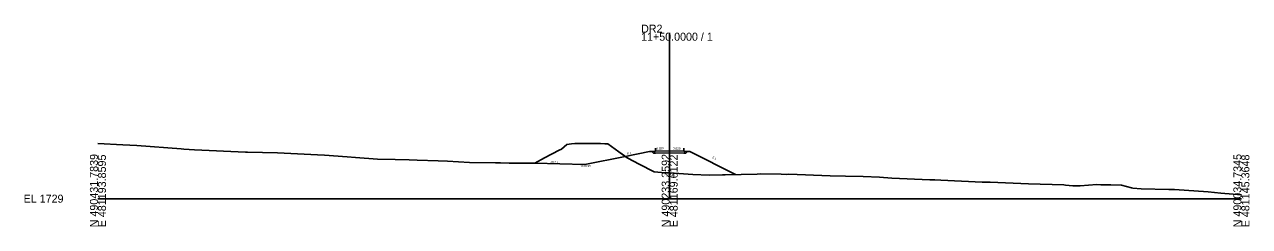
# Model space of a CAD drawing. Extents: x -26 to 403, y -10 to 2576.
# Drawn here: x -25.7 to 402.8, y 1490.3 to 1560.8 of the extents above; entities that cross this region are included whole.
import ezdxf

# ---------------------------------------------------------------- set-up
doc = ezdxf.new("R2010")
doc.units = 0
for name, color, linetype in [('Exist Cross Section Cell', 7, 'Continuous'), ('Exist XS Center Line Elevation Label', 7, 'Continuous'), ('Exist XS Ground Line', 7, 'Continuous'), ('Prop Road Sect_ Boring - Header (ID Tx)', 7, 'Continuous'), ('Prop XS Ditch Standard Text', 7, 'Continuous'), ('Prop XS Dump Level', 7, 'Continuous'), ('Prop XS Earthwork Shape', 7, 'Continuous'), ('Prop XS EOT Tick Mark', 7, 'Continuous'), ('Prop XS Finish Grade', 7, 'Continuous'), ('Prop XS Finish Grade Earthwork', 7, 'Continuous'), ('Prop XS Finish Grade Pavement', 7, 'Continuous'), ('Prop XS Pvmt Edge Slope', 7, 'Continuous'), ('Prop XS SE Text', 7, 'Continuous'), ('Prop XS Side Slope Text', 7, 'Continuous'), ('Prop XS Subgrade Earthwork', 7, 'Continuous')]:
    doc.layers.add(name, color=color, linetype=linetype)

msp = doc.modelspace()

# ---------------------------------------------------------------- linework, layer by layer
at = {"layer": 'Exist Cross Section Cell'}
for p, q in [((200, 1500), (200, 1557.94)), ((0, 1500), (200, 1500)), ((200, 1500), (400, 1500))]:
    msp.add_line(p, q, dxfattribs=at)
at = {"layer": 'Exist XS Ground Line'}
msp.add_lwpolyline([(0, 1519.31), (8.74, 1518.81), (13.56, 1518.54), (29.14, 1517.35), (30.03, 1517.29), (33.75, 1517.09), (51.66, 1516.26), (52.26, 1516.2), (62.83, 1515.95), (76.82, 1515.27), (79.27, 1515.16), (87.16, 1514.55), (90.07, 1514.37), (97.8, 1513.81), (103.94, 1513.71), (108.82, 1513.56), (111.71, 1513.43), (119.03, 1513.2), (122.32, 1513.05), (130.01, 1512.67), (139.06, 1512.48), (140.2, 1512.46), (140.88, 1512.49), (143.86, 1512.43), (152.84, 1512.38), (156.17, 1514.28), (161.31, 1516.93), (162.12, 1517.34), (164.07, 1518.92), (165.62, 1519.11), (166.82, 1519.26), (169.11, 1519.25), (175.8, 1519.23), (177.3, 1519.12), (178.39, 1519.09), (182.19, 1516.39), (185.34, 1514.15), (189.37, 1511.99), (194.6, 1509.38), (198.43, 1509.08), (200, 1508.98), (208.12, 1508.44), (213.79, 1508.26), (230.62, 1508.61), (231.88, 1508.62), (238.95, 1508.52), (240.84, 1508.49), (241.68, 1508.52), (256.16, 1507.93), (261.46, 1507.87), (267.67, 1507.73), (273.45, 1507.53), (277.74, 1507.2), (291.02, 1506.62), (292.78, 1506.56), (294.82, 1506.47), (309.34, 1505.77), (310.62, 1505.8), (312.17, 1505.72), (325.58, 1505.14), (337.91, 1504.8), (338.46, 1504.76), (341.06, 1504.54), (343.6, 1504.5), (349.42, 1504.96), (350.84, 1504.78), (354.32, 1504.89), (358.09, 1504.66), (361.61, 1503.77), (361.99, 1503.69), (364.96, 1503.45), (374.67, 1503.26), (375.3, 1503.21), (376.62, 1503.16), (388.4, 1502.42), (392.84, 1501.92), (400, 1501.31)], dxfattribs=at)
at = {"layer": 'Prop Road Sect_ Boring - Header (ID Tx)'}
for points in [[(195, 1516.61), (194.32, 1515.93), (193.74, 1516.51)], [(205.68, 1515.93), (206.26, 1516.51), (205, 1516.61)]]:
    msp.add_lwpolyline(points, close=True, dxfattribs=at)
at = {"layer": 'Prop XS Dump Level'}
for p, q in [((195, 1516.61), (200, 1516.71)), ((200, 1516.71), (205, 1516.61))]:
    msp.add_line(p, q, dxfattribs=at)
at = {"layer": 'Prop XS Earthwork Shape'}
for p, q in [((165.62, 1519.11), (164.07, 1518.92)), ((156.17, 1514.28), (152.84, 1512.38)), ((161.31, 1516.93), (156.17, 1514.28)), ((170.38, 1511.95), (184.49, 1514.76)), ((184.49, 1514.76), (182.19, 1516.39)), ((152.84, 1512.38), (170.38, 1511.95))]:
    msp.add_line(p, q, dxfattribs=at)
for points in [[(164.07, 1518.92), (162.12, 1517.34), (161.31, 1516.93)], [(169.11, 1519.25), (166.82, 1519.26), (165.62, 1519.11)], [(177.3, 1519.12), (175.8, 1519.23), (169.11, 1519.25)], [(182.19, 1516.39), (178.39, 1519.09), (177.3, 1519.12)], [(184.49, 1514.76), (184.49, 1514.76)]]:
    msp.add_lwpolyline(points, dxfattribs=at)
msp.add_lwpolyline([(195, 1515.94), (194.32, 1515.93), (193.74, 1516.51), (193, 1516.45), (184.49, 1514.76), (185.34, 1514.15), (189.37, 1511.99), (194.6, 1509.38), (198.43, 1509.08), (200, 1508.98), (208.12, 1508.44), (213.79, 1508.26), (222.99, 1508.45), (207, 1516.45), (206.26, 1516.51), (205.68, 1515.93), (205, 1515.94), (200, 1516.04)], close=True, dxfattribs=at)
at = {"layer": 'Prop XS EOT Tick Mark'}
for p, q in [((195, 1516.61), (195, 1517.61)), ((205, 1516.61), (205, 1517.61))]:
    msp.add_line(p, q, dxfattribs=at)
at = {"layer": 'Prop XS Finish Grade'}
for p, q in [((195, 1516.61), (193.74, 1516.51)), ((205, 1516.61), (206.26, 1516.51))]:
    msp.add_line(p, q, dxfattribs=at)
at = {"layer": 'Prop XS Finish Grade Earthwork'}
for p, q in [((170.38, 1511.95), (184.49, 1514.76)), ((193, 1516.45), (184.49, 1514.76)), ((193.74, 1516.51), (193, 1516.45)), ((206.26, 1516.51), (207, 1516.45)), ((207, 1516.45), (222.99, 1508.45)), ((152.84, 1512.38), (170.38, 1511.95))]:
    msp.add_line(p, q, dxfattribs=at)
at = {"layer": 'Prop XS Finish Grade Pavement'}
for p, q in [((195, 1516.61), (200, 1516.71)), ((200, 1516.71), (205, 1516.61))]:
    msp.add_line(p, q, dxfattribs=at)
at = {"layer": 'Prop XS Pvmt Edge Slope'}
for p, q in [((195, 1516.61), (194.32, 1515.93)), ((205, 1516.61), (205.68, 1515.93))]:
    msp.add_line(p, q, dxfattribs=at)
at = {"layer": 'Prop XS Subgrade Earthwork'}
for p, q in [((194.32, 1515.93), (193.74, 1516.51)), ((195, 1515.94), (194.32, 1515.93)), ((200, 1516.04), (195, 1515.94)), ((205, 1515.94), (200, 1516.04)), ((205, 1515.94), (205.68, 1515.93)), ((205.68, 1515.93), (206.26, 1516.51))]:
    msp.add_line(p, q, dxfattribs=at)

# ---------------------------------------------------------------- texts
at = {"layer": 'Exist Cross Section Cell'}
for s, p in [('DR2', (190, 1557.94)), ('11+50.0000 / 1', (190, 1555.14)), ('EL 1729', (-26, 1498.6))]:
    msp.add_text(s, height=2.8, dxfattribs=at).set_placement(p)
for s, p in [('N 490431.7839', (0, 1490)), ('E 481193.8595', (2.8, 1490)), ('N 490233.2592', (200, 1490)), ('E 481169.6122', (202.8, 1490)), ('N 490034.7345', (400, 1490)), ('E 481145.3648', (402.8, 1490))]:
    msp.add_text(s, height=2.8, rotation=90, dxfattribs=at).set_placement(p)
at = {"layer": 'Exist XS Center Line Elevation Label'}
msp.add_text('1737.98', height=0.75, dxfattribs=at).set_placement((198.07, 1507.63))
at = {"layer": 'Prop XS Ditch Standard Text'}
msp.add_text('1740.95', height=0.75, dxfattribs=at).set_placement((168.71, 1511.02))
at = {"layer": 'Prop XS Dump Level'}
for p in [(193, 1516.41), (207, 1516.41)]:
    msp.add_text('Case1', height=0.04, dxfattribs=at).set_placement(p)
at = {"layer": 'Prop XS SE Text'}
for rotation, p in [(1.1458, (195.35, 1517.13)), (358.8542, (201.18, 1517.18))]:
    msp.add_text('0.020', height=0.75, rotation=rotation, dxfattribs=at).set_placement(p)
at = {"layer": 'Prop XS Side Slope Text'}
for s, rotation, p in [('40.7:1', 359.1117, (158.31, 1512.43)), ('6:1', 9.4623, (185.14, 1515.37)), ('2:1', 333.4349, (214.85, 1514.2))]:
    msp.add_text(s, height=0.75, rotation=rotation, dxfattribs=at).set_placement(p)

doc.saveas('drawing.dxf')
